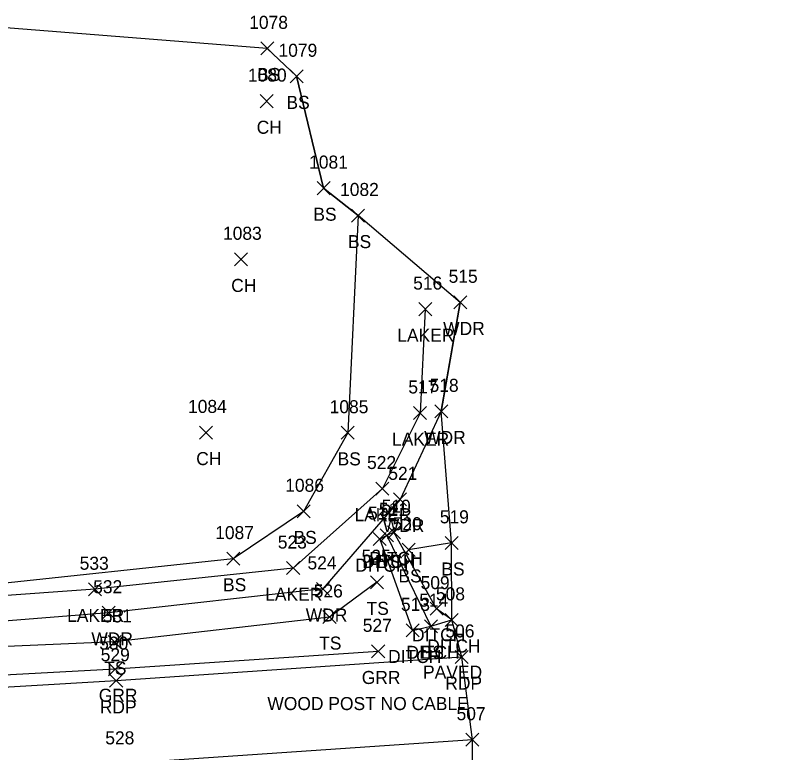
# Model space of a CAD drawing. Extents: x 1715662 to 1717487, y 887396 to 890004.
# Drawn here: x 1717358.8 to 1717478.7, y 888260.9 to 888373.9 of the extents above; entities that cross this region are included whole.
import ezdxf

# ---------------------------------------------------------------- set-up
doc = ezdxf.new("R2010")
doc.units = 0
for name, color, linetype in [('D_A', 7, 'Continuous'), ('D_C', 7, 'Continuous'), ('D_I', 7, 'Continuous'), ('D_TIC', 7, 'Continuous'), ('DD', 7, 'Continuous'), ('L_A', 7, 'Continuous'), ('L_I', 7, 'Continuous'), ('L_TIC', 7, 'Continuous'), ('LAWA', 7, 'Continuous'), ('LAWE', 7, 'Continuous'), ('LELB', 7, 'Continuous'), ('LSOGP', 7, 'Continuous'), ('P_A', 7, 'Continuous'), ('P_I', 7, 'Continuous'), ('P_TIC', 7, 'Continuous'), ('PET', 7, 'Continuous'), ('PRC', 7, 'Continuous'), ('R_A', 7, 'Continuous'), ('R_C', 7, 'Continuous'), ('R_I', 7, 'Continuous'), ('R_TIC', 7, 'Continuous'), ('RGR', 7, 'Continuous')]:
    doc.layers.add(name, color=color, linetype=linetype)

msp = doc.modelspace()

# ---------------------------------------------------------------- linework, layer by layer
at = {"layer": 'D_TIC'}
for points in [[(1717414.79, 888293.22), (1717416.79, 888295.22)], [(1717416.79, 888293.22), (1717414.79, 888295.22)], [(1717415.87, 888293.7), (1717417.87, 888295.7)], [(1717417.87, 888293.7), (1717415.87, 888295.7)], [(1717413.7, 888292.65), (1717415.7, 888294.65)], [(1717415.7, 888292.65), (1717413.7, 888294.65)], [(1717422.42, 888281.98), (1717424.42, 888283.98)], [(1717424.42, 888281.98), (1717422.42, 888283.98)], [(1717424.76, 888280.26), (1717426.76, 888282.26)], [(1717426.76, 888280.26), (1717424.76, 888282.26)], [(1717418.75, 888278.65), (1717420.75, 888280.65)], [(1717420.75, 888278.65), (1717418.75, 888280.65)], [(1717421.55, 888279.29), (1717423.55, 888281.29)], [(1717423.55, 888279.29), (1717421.55, 888281.29)]]:
    msp.add_lwpolyline(points, dxfattribs=at)
at = {"layer": 'DD'}
msp.add_lwpolyline([(1717425.76, 888281.26), (1717423.42, 888282.98), (1717416.87, 888294.7), (1717415.79, 888294.22), (1717414.7, 888293.65), (1717419.75, 888279.65), (1717422.55, 888280.29)], dxfattribs=at)
at = {"layer": 'L_TIC'}
for points in [[(1717396.44, 888367.91), (1717398.44, 888369.91)], [(1717398.44, 888367.91), (1717396.44, 888369.91)], [(1717400.94, 888363.63), (1717402.94, 888365.63)], [(1717402.94, 888363.63), (1717400.94, 888365.63)], [(1717396.32, 888359.82), (1717398.32, 888361.82)], [(1717398.32, 888359.82), (1717396.32, 888361.82)], [(1717405.07, 888346.48), (1717407.07, 888348.48)], [(1717407.07, 888346.48), (1717405.07, 888348.48)], [(1717410.38, 888342.28), (1717412.38, 888344.28)], [(1717412.38, 888342.28), (1717410.38, 888344.28)], [(1717392.42, 888335.56), (1717394.42, 888337.56)], [(1717394.42, 888335.56), (1717392.42, 888337.56)], [(1717426.07, 888328.96), (1717428.07, 888330.96)], [(1717428.07, 888328.96), (1717426.07, 888330.96)], [(1717420.68, 888327.92), (1717422.68, 888329.92)], [(1717422.68, 888327.92), (1717420.68, 888329.92)], [(1717423.15, 888312.24), (1717425.15, 888314.24)], [(1717425.15, 888312.24), (1717423.15, 888314.24)], [(1717419.89, 888311.99), (1717421.89, 888313.99)], [(1717421.89, 888311.99), (1717419.89, 888313.99)], [(1717387.04, 888309), (1717389.04, 888311)], [(1717389.04, 888309), (1717387.04, 888311)], [(1717408.79, 888308.96), (1717410.79, 888310.96)], [(1717410.79, 888308.96), (1717408.79, 888310.96)], [(1717414.11, 888300.4), (1717416.11, 888302.4)], [(1717416.11, 888300.4), (1717414.11, 888302.4)], [(1717416.81, 888298.74), (1717418.81, 888300.74)], [(1717418.81, 888298.74), (1717416.81, 888300.74)], [(1717402.02, 888296.91), (1717404.02, 888298.91)], [(1717404.02, 888296.91), (1717402.02, 888298.91)], [(1717414.79, 888293.22), (1717416.79, 888295.22)], [(1717416.79, 888293.22), (1717414.79, 888295.22)], [(1717424.72, 888292.07), (1717426.72, 888294.07)], [(1717426.72, 888292.07), (1717424.72, 888294.07)], [(1717418.13, 888291.01), (1717420.13, 888293.01)], [(1717420.13, 888291.01), (1717418.13, 888293.01)], [(1717391.21, 888289.65), (1717393.21, 888291.65)], [(1717393.21, 888289.65), (1717391.21, 888291.65)], [(1717400.41, 888288.2), (1717402.41, 888290.2)], [(1717402.41, 888288.2), (1717400.41, 888290.2)], [(1717413.27, 888286.03), (1717415.27, 888288.03)], [(1717415.27, 888286.03), (1717413.27, 888288.03)], [(1717370, 888284.95), (1717372, 888286.95)], [(1717372, 888284.95), (1717370, 888286.95)], [(1717404.98, 888285.01), (1717406.98, 888287.01)], [(1717406.98, 888285.01), (1717404.98, 888287.01)], [(1717372.07, 888281.35), (1717374.07, 888283.35)], [(1717374.07, 888281.35), (1717372.07, 888283.35)], [(1717405.99, 888280.7), (1717407.99, 888282.7)], [(1717407.99, 888280.7), (1717405.99, 888282.7)], [(1717421.55, 888279.29), (1717423.55, 888281.29)], [(1717423.55, 888279.29), (1717421.55, 888281.29)], [(1717372.99, 888276.88), (1717374.99, 888278.88)], [(1717374.99, 888276.88), (1717372.99, 888278.88)]]:
    msp.add_lwpolyline(points, dxfattribs=at)
at = {"layer": 'LAWA'}
msp.add_lwpolyline([(1717427.07, 888329.96), (1717424.15, 888313.24), (1717417.81, 888299.74), (1717405.98, 888286.01), (1717373.07, 888282.35), (1717318.58, 888278), (1717270.11, 888276.06), (1717231.85, 888274.55), (1717204.52, 888271.65)], dxfattribs=at)
at = {"layer": 'LAWE'}
msp.add_lwpolyline([(1717421.68, 888328.92), (1717420.89, 888312.99), (1717415.11, 888301.4), (1717401.41, 888289.2), (1717371, 888285.95), (1717321.69, 888282.44), (1717271.81, 888279.67), (1717230.21, 888280.53), (1717194.5, 888279.04), (1717177.12, 888274.47), (1717174.06, 888271.23), (1717172.86, 888266.22)], dxfattribs=at)
at = {"layer": 'LELB'}
for points in [[(1717397.44, 888368.91), (1717401.94, 888364.63), (1717406.07, 888347.48), (1717411.38, 888343.28), (1717409.79, 888309.96), (1717403.02, 888297.91), (1717392.21, 888290.65), (1717353.83, 888286.56), (1717306.03, 888285.64), (1717272.45, 888283.32), (1717220.2, 888284.1), (1717193.83, 888280.31), (1717176.82, 888276.72), (1717169.82, 888270.77)], [(1717415.79, 888294.22), (1717422.55, 888280.29)], [(1717425.72, 888293.07), (1717419.13, 888292.01)], [(1717414.27, 888287.03), (1717406.99, 888281.7), (1717373.99, 888277.88), (1717318.52, 888275.5), (1717269.66, 888272.61), (1717230.91, 888271.26), (1717203.91, 888268.9), (1717185.06, 888265.29), (1717179.22, 888264.43), (1717179.32, 888261.72)], [(1717422.55, 888280.29), (1717425.76, 888281.26)]]:
    msp.add_lwpolyline(points, dxfattribs=at)
at = {"layer": 'LSOGP'}
msp.add_lwpolyline([(1717478.65, 888184.02), (1717438.03, 888204.25), (1717428.73, 888210.05), (1717429.05, 888212.6), (1717429.57, 888226.27), (1717430.27, 888234.68), (1717429.72, 888242.9), (1717429.56, 888243.99), (1717429.73, 888244.54), (1717429.07, 888249.37), (1717429.05, 888249.53), (1717428.93, 888262.88), (1717427.28, 888275.56), (1717425.76, 888281.26), (1717425.72, 888293.07), (1717424.15, 888313.25), (1717427.07, 888329.96), (1717411.38, 888343.28), (1717406.07, 888347.48), (1717401.94, 888364.63), (1717397.44, 888368.91), (1717347.56, 888372.82)], dxfattribs=at)
at = {"layer": 'P_TIC'}
for points in [[(1717426.27, 888274.57), (1717428.27, 888276.57)], [(1717428.27, 888274.57), (1717426.27, 888276.57)], [(1717373.24, 888270.92), (1717375.24, 888272.92)], [(1717375.24, 888270.92), (1717373.24, 888272.92)], [(1717427.93, 888261.88), (1717429.93, 888263.88)], [(1717429.93, 888261.88), (1717427.93, 888263.88)]]:
    msp.add_lwpolyline(points, dxfattribs=at)
at = {"layer": 'PET'}
msp.add_lwpolyline([(1717427.27, 888275.57), (1717374.24, 888271.92), (1717317.86, 888268.58), (1717270, 888265.54), (1717231.18, 888263.33), (1717177.06, 888260.69), (1717177.8, 888248.05), (1717178.6, 888236.51), (1717214.03, 888237.98), (1717254.52, 888239.74), (1717289.28, 888241.31), (1717339.42, 888243.96), (1717387.67, 888246.79), (1717419.3, 888248.63), (1717429.05, 888249.53)], dxfattribs=at)
at = {"layer": 'PRC'}
msp.add_lwpolyline([(1717428.93, 888262.88), (1717374.93, 888259.17), (1717318.78, 888255.52), (1717271.43, 888252.69), (1717231.27, 888251.09), (1717177.8, 888248.05)], dxfattribs=at)
at = {"layer": 'R_TIC'}
for points in [[(1717413.46, 888275.43), (1717415.46, 888277.43)], [(1717415.46, 888275.43), (1717413.46, 888277.43)], [(1717373.09, 888272.7), (1717375.09, 888274.7)], [(1717375.09, 888272.7), (1717373.09, 888274.7)]]:
    msp.add_lwpolyline(points, dxfattribs=at)
at = {"layer": 'RGR'}
msp.add_lwpolyline([(1717414.46, 888276.43), (1717374.09, 888273.7), (1717318.26, 888270.69), (1717269.91, 888267.54), (1717230.71, 888265.34), (1717183.33, 888262.06)], dxfattribs=at)

# ---------------------------------------------------------------- texts
at = {"layer": 'D_A'}
for p in [(1717412.02, 888289.22), (1717413.11, 888289.7), (1717410.93, 888288.65), (1717419.66, 888277.98), (1717422, 888276.26), (1717418.79, 888275.29), (1717415.98, 888274.65)]:
    msp.add_text('DITCH', height=2, dxfattribs=at).set_placement(p)
at = {"layer": 'D_C'}
msp.add_text('PAVED', height=2, dxfattribs=at).set_placement((1717421.35, 888272.26))
at = {"layer": 'D_I'}
for s, p in [('510', (1717414.99, 888297.7)), ('512', (1717412.9, 888296.65)), ('511', (1717414.56, 888297.22)), ('509', (1717420.97, 888285.98)), ('514', (1717420.76, 888283.29)), ('508', (1717423.32, 888284.26)), ('513', (1717417.95, 888282.65))]:
    msp.add_text(s, height=2, dxfattribs=at).set_placement(p)
at = {"layer": 'L_A'}
for s, p in [('BS', (1717395.88, 888363.91)), ('BS', (1717400.38, 888359.63)), ('CH', (1717395.81, 888355.82)), ('BS', (1717404.51, 888342.48)), ('BS', (1717409.82, 888338.28)), ('CH', (1717391.9, 888331.56)), ('WDR', (1717424.43, 888324.96)), ('LAKER', (1717417.39, 888323.92)), ('LAKER', (1717416.59, 888307.99)), ('WDR', (1717421.51, 888308.24)), ('CH', (1717386.53, 888305)), ('BS', (1717408.23, 888304.96)), ('LAKER', (1717410.82, 888296.4)), ('WDR', (1717415.17, 888294.74)), ('BS', (1717401.46, 888292.91)), ('BS', (1717414.23, 888289.22)), ('BS', (1717424.16, 888288.07)), ('BS', (1717417.57, 888287.01)), ('BS', (1717390.65, 888285.65)), ('LAKER', (1717397.12, 888284.2)), ('TS', (1717412.68, 888282.03)), ('LAKER', (1717366.71, 888280.95)), ('WDR', (1717403.34, 888281.01)), ('WDR', (1717370.43, 888277.35)), ('TS', (1717405.4, 888276.7)), ('BS', (1717420.99, 888275.29)), ('TS', (1717372.4, 888272.88))]:
    msp.add_text(s, height=2, dxfattribs=at).set_placement(p)
at = {"layer": 'L_I'}
for s, p in [('1078', (1717394.66, 888371.91)), ('1079', (1717399.16, 888367.63)), ('1080', (1717394.46, 888363.82)), ('1081', (1717403.86, 888350.48)), ('1082', (1717408.61, 888346.28)), ('1083', (1717390.64, 888339.56)), ('515', (1717425.27, 888332.96)), ('516', (1717419.83, 888331.92)), ('517', (1717419.09, 888315.99)), ('518', (1717422.35, 888316.24)), ('1084', (1717385.27, 888313)), ('1085', (1717407.01, 888312.96)), ('522', (1717412.75, 888304.4)), ('521', (1717416.01, 888302.74)), ('1086', (1717400.19, 888300.91)), ('511', (1717414.56, 888297.22)), ('519', (1717423.92, 888296.07)), ('520', (1717416.68, 888295.01)), ('1087', (1717389.44, 888293.65)), ('523', (1717399.05, 888292.2)), ('525', (1717411.91, 888290.03)), ('533', (1717368.64, 888288.95)), ('524', (1717403.61, 888289.01)), ('532', (1717370.71, 888285.35)), ('526', (1717404.57, 888284.7)), ('514', (1717420.76, 888283.29)), ('531', (1717372.19, 888280.88))]:
    msp.add_text(s, height=2, dxfattribs=at).set_placement(p)
at = {"layer": 'P_A'}
for p in [(1717424.76, 888270.57), (1717371.73, 888266.92)]:
    msp.add_text('RDP', height=2, dxfattribs=at).set_placement(p)
at = {"layer": 'P_I'}
for s, p in [('506', (1717424.78, 888278.57)), ('529', (1717371.87, 888274.92)), ('507', (1717426.49, 888265.88)), ('528', (1717372.57, 888262.17))]:
    msp.add_text(s, height=2, dxfattribs=at).set_placement(p)
at = {"layer": 'R_A'}
for p in [(1717411.94, 888271.43), (1717371.57, 888268.7)]:
    msp.add_text('GRR', height=2, dxfattribs=at).set_placement(p)
at = {"layer": 'R_C'}
msp.add_text('WOOD POST NO CABLE', height=2, dxfattribs=at).set_placement((1717397.45, 888267.43))
at = {"layer": 'R_I'}
for s, p in [('527', (1717412.09, 888279.43)), ('530', (1717371.64, 888276.7))]:
    msp.add_text(s, height=2, dxfattribs=at).set_placement(p)

doc.saveas('drawing.dxf')
